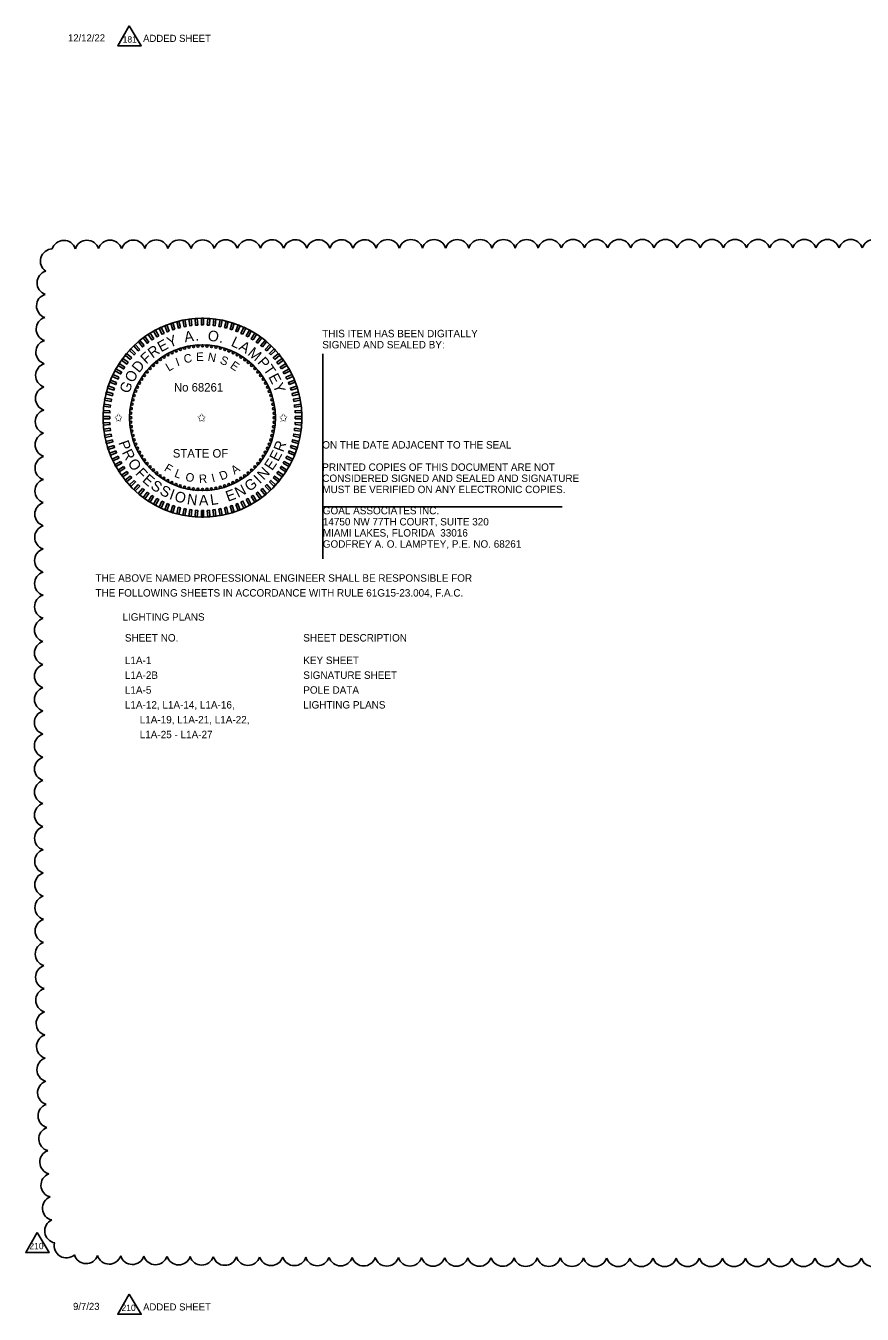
# Model space of a CAD drawing. Extents: x -811.2 to -795.1, y -2238.2 to -2204.
# Drawn here: x -811.16 to -803.27, y -2237.98 to -2225.83 of the extents above; entities that cross this region are included whole.
import ezdxf

# ---------------------------------------------------------------- set-up
doc = ezdxf.new("R2010")
doc.units = 0
for name, color, linetype in [('AdhocPoint_dp', 7, 'Continuous'), ('Cloud_dp', 7, 'Continuous'), ('PlotBorder_dp', 7, 'Continuous'), ('TextMinor', 7, 'Continuous'), ('TextMisc', 7, 'Continuous'), ('TextShtNo', 7, 'Continuous')]:
    doc.layers.add(name, color=color, linetype=linetype)

msp = doc.modelspace()

# ---------------------------------------------------------------- linework, layer by layer
at = {"layer": 'AdhocPoint_dp'}
for p, q in [((-808.355, -2228.92), (-808.355, -2230.855)), ((-808.355, -2230.365), (-806.098, -2230.365))]:
    msp.add_line(p, q, dxfattribs=at)
at = {"layer": 'Cloud_dp'}
for points in [[(-810.181, -2225.827), (-810.289, -2226.015), (-810.068, -2226.015)], [(-811.049, -2237.21), (-811.157, -2237.398), (-810.937, -2237.398)], [(-810.181, -2237.792), (-810.289, -2237.98), (-810.068, -2237.98)]]:
    msp.add_lwpolyline(points, close=True, dxfattribs=at)
for centre, start, end in [((-810.905, -2228.046), 91.4771, 236.4771), ((-810.798, -2227.965), 18.0566, 163.0566), ((-810.58, -2227.964), 17.7998, 162.7998), ((-810.362, -2227.963), 17.7187, 162.7187), ((-810.143, -2227.962), 17.6743, 162.6743), ((-809.925, -2227.961), 17.6451, 162.6451), ((-809.707, -2227.961), 17.624, 162.624), ((-809.488, -2227.961), 17.6079, 162.6079), ((-809.27, -2227.96), 17.5951, 162.5951), ((-809.052, -2227.96), 17.5845, 162.5845), ((-808.834, -2227.959), 17.5756, 162.5756), ((-808.615, -2227.959), 17.568, 162.568), ((-808.397, -2227.959), 17.5614, 162.5614), ((-808.179, -2227.959), 17.5556, 162.5556), ((-807.96, -2227.959), 17.5505, 162.5505), ((-807.742, -2227.958), 17.5459, 162.5459), ((-807.524, -2227.958), 17.5417, 162.5417), ((-807.305, -2227.958), 17.5379, 162.5379), ((-807.087, -2227.958), 17.5344, 162.5344), ((-806.869, -2227.958), 17.5313, 162.5313), ((-806.65, -2227.958), 17.5283, 162.5283), ((-806.432, -2227.958), 17.5256, 162.5256), ((-806.214, -2227.957), 17.5231, 162.5231), ((-805.995, -2227.957), 17.5207, 162.5207), ((-805.777, -2227.957), 17.5185, 162.5185), ((-805.559, -2227.957), 17.5164, 162.5164), ((-805.34, -2227.957), 17.5145, 162.5145), ((-805.122, -2227.957), 17.5126, 162.5126), ((-804.904, -2227.957), 17.5109, 162.5109), ((-804.685, -2227.957), 17.5092, 162.5092), ((-804.467, -2227.957), 17.5077, 162.5077), ((-804.249, -2227.957), 17.5062, 162.5062), ((-804.03, -2227.957), 17.5048, 162.5048), ((-803.812, -2227.957), 17.5034, 162.5034), ((-803.594, -2227.957), 17.5021, 162.5021), ((-803.375, -2227.957), 17.5009, 162.5009), ((-803.157, -2227.957), 17.5, 162.5), ((-810.937, -2228.252), 105.908, 250.908), ((-810.942, -2228.47), 106.4168, 251.4168), ((-810.945, -2228.688), 106.6762, 251.6762), ((-810.948, -2228.906), 106.841, 251.841), ((-810.95, -2229.124), 106.9576, 251.9576), ((-810.952, -2229.343), 107.0457, 252.0457), ((-810.954, -2229.561), 107.1154, 252.1154), ((-810.955, -2229.779), 107.1722, 252.1722), ((-810.956, -2229.998), 107.2198, 252.2198), ((-810.957, -2230.216), 107.2603, 252.2603), ((-810.958, -2230.434), 107.2954, 252.2954), ((-810.959, -2230.652), 107.3262, 252.3262), ((-810.96, -2230.871), 107.3535, 252.3535), ((-810.96, -2231.089), 107.3779, 252.3779), ((-810.96, -2231.307), 107.3998, 252.3998), ((-810.961, -2231.526), 107.4198, 252.4198), ((-810.961, -2231.744), 107.438, 252.438), ((-810.961, -2231.962), 107.4547, 252.4547), ((-810.961, -2232.181), 107.4701, 252.4701), ((-810.962, -2232.399), 107.4843, 252.4843), ((-810.962, -2232.617), 107.499, 252.499), ((-810.961, -2232.836), 107.5356, 252.5356), ((-810.961, -2233.054), 107.5822, 252.5822), ((-810.961, -2233.272), 107.6325, 252.6325), ((-810.96, -2233.49), 107.6869, 252.6869), ((-810.959, -2233.709), 107.7461, 252.7461), ((-810.958, -2233.927), 107.8108, 252.8108), ((-810.957, -2234.145), 107.8818, 252.8818), ((-810.955, -2234.364), 107.9604, 252.9604), ((-810.954, -2234.582), 108.0479, 253.0479), ((-810.951, -2234.8), 108.1461, 253.1461), ((-810.949, -2235.018), 108.2576, 253.2576), ((-810.945, -2235.237), 108.3854, 253.3854), ((-810.942, -2235.455), 108.534, 253.534), ((-810.938, -2235.673), 108.7099, 253.7099), ((-810.932, -2235.891), 108.9225, 253.9225), ((-810.927, -2236.109), 109.1867, 254.1867), ((-810.92, -2236.327), 109.5275, 254.5275), ((-810.911, -2236.545), 109.9909, 254.9909), ((-810.9, -2236.763), 110.6749, 255.6749), ((-810.886, -2236.98), 111.8417, 256.8417), ((-810.864, -2237.195), 114.6718, 259.6718), ((-810.774, -2237.335), 166.2299, 311.2299), ((-810.588, -2237.389), 196.1072, 341.1072), ((-810.37, -2237.394), 196.5738, 341.5738), ((-810.152, -2237.397), 196.7877, 341.7877), ((-809.934, -2237.399), 196.9179, 341.9179), ((-809.715, -2237.401), 197.008, 342.008), ((-809.497, -2237.403), 197.075, 342.075), ((-809.279, -2237.405), 197.1274, 342.1274), ((-809.061, -2237.406), 197.1699, 342.1699), ((-808.842, -2237.407), 197.2052, 342.2052), ((-808.624, -2237.408), 197.2352, 342.2352), ((-808.406, -2237.409), 197.261, 342.261), ((-808.187, -2237.41), 197.2836, 342.2836), ((-807.969, -2237.411), 197.3036, 342.3036), ((-807.751, -2237.412), 197.3214, 342.3214), ((-807.532, -2237.412), 197.3374, 342.3374), ((-807.314, -2237.413), 197.3519, 342.3519), ((-807.096, -2237.413), 197.3651, 342.3651), ((-806.878, -2237.414), 197.3773, 342.3773), ((-806.659, -2237.414), 197.3884, 342.3884), ((-806.441, -2237.415), 197.3987, 342.3987), ((-806.223, -2237.415), 197.4083, 342.4083), ((-806.004, -2237.415), 197.4172, 342.4172), ((-805.786, -2237.416), 197.4256, 342.4256), ((-805.568, -2237.416), 197.4334, 342.4334), ((-805.349, -2237.416), 197.4407, 342.4407), ((-805.131, -2237.417), 197.4476, 342.4476), ((-804.913, -2237.417), 197.4542, 342.4542), ((-804.694, -2237.417), 197.4604, 342.4604), ((-804.476, -2237.417), 197.4662, 342.4662), ((-804.258, -2237.417), 197.4718, 342.4718), ((-804.039, -2237.417), 197.4771, 342.4771), ((-803.821, -2237.417), 197.4821, 342.4821), ((-803.603, -2237.417), 197.487, 342.487), ((-803.384, -2237.417), 197.4916, 342.4916), ((-803.166, -2237.417), 197.496, 342.496)]:
    msp.add_arc(centre, 0.114, start, end, dxfattribs=at)
at = {"layer": 'TextMinor'}
for radius in [0.938, 0.688]:
    msp.add_circle((-809.49, -2229.524), radius, dxfattribs=at)
at = {"layer": 'TextShtNo'}
for p, q in [((-809.5, -2230.461), (-809.5, -2230.399)), ((-809.49, -2230.461), (-809.49, -2230.399)), ((-809.48, -2230.461), (-809.48, -2230.399))]:
    msp.add_line(p, q, dxfattribs=at)
for points in [[(-809.853, -2228.728), (-809.872, -2228.736), (-809.898, -2228.68), (-809.88, -2228.671)], [(-809.803, -2228.706), (-809.822, -2228.714), (-809.845, -2228.656), (-809.826, -2228.648)], [(-809.751, -2228.688), (-809.77, -2228.695), (-809.789, -2228.635), (-809.77, -2228.629)], [(-809.698, -2228.674), (-809.717, -2228.679), (-809.733, -2228.618), (-809.713, -2228.613)], [(-809.644, -2228.662), (-809.664, -2228.666), (-809.676, -2228.605), (-809.656, -2228.601)], [(-809.59, -2228.654), (-809.61, -2228.657), (-809.618, -2228.595), (-809.598, -2228.592)], [(-809.535, -2228.65), (-809.555, -2228.651), (-809.559, -2228.589), (-809.539, -2228.588)], [(-809.48, -2228.649), (-809.5, -2228.649), (-809.5, -2228.586), (-809.48, -2228.586)], [(-809.425, -2228.651), (-809.445, -2228.65), (-809.441, -2228.588), (-809.421, -2228.589)], [(-809.37, -2228.657), (-809.39, -2228.654), (-809.383, -2228.592), (-809.363, -2228.595)], [(-809.316, -2228.666), (-809.336, -2228.662), (-809.324, -2228.601), (-809.304, -2228.605)], [(-809.263, -2228.679), (-809.282, -2228.674), (-809.267, -2228.613), (-809.247, -2228.618)], [(-809.21, -2228.695), (-809.229, -2228.689), (-809.21, -2228.629), (-809.191, -2228.635)], [(-809.159, -2228.714), (-809.177, -2228.707), (-809.154, -2228.649), (-809.136, -2228.656)], [(-809.108, -2228.736), (-809.127, -2228.728), (-809.1, -2228.671), (-809.082, -2228.68)], [(-810.04, -2228.843), (-810.056, -2228.856), (-810.095, -2228.808), (-810.08, -2228.795)], [(-809.996, -2228.81), (-810.013, -2228.822), (-810.049, -2228.771), (-810.033, -2228.759)], [(-809.95, -2228.78), (-809.967, -2228.79), (-810.001, -2228.738), (-809.984, -2228.727)], [(-809.903, -2228.752), (-809.92, -2228.762), (-809.951, -2228.707), (-809.933, -2228.697)], [(-809.06, -2228.762), (-809.077, -2228.752), (-809.047, -2228.697), (-809.03, -2228.707)], [(-809.013, -2228.79), (-809.03, -2228.78), (-808.996, -2228.727), (-808.979, -2228.738)], [(-808.968, -2228.822), (-808.984, -2228.81), (-808.947, -2228.76), (-808.931, -2228.771)], [(-808.925, -2228.856), (-808.94, -2228.843), (-808.9, -2228.795), (-808.885, -2228.808)], [(-810.158, -2228.958), (-810.171, -2228.974), (-810.219, -2228.934), (-810.206, -2228.918)], [(-810.121, -2228.917), (-810.135, -2228.932), (-810.18, -2228.889), (-810.167, -2228.875)], [(-810.082, -2228.879), (-810.096, -2228.893), (-810.139, -2228.847), (-810.124, -2228.833)], [(-808.884, -2228.893), (-808.898, -2228.879), (-808.856, -2228.834), (-808.841, -2228.847)], [(-808.845, -2228.932), (-808.859, -2228.918), (-808.814, -2228.875), (-808.8, -2228.89)], [(-808.809, -2228.974), (-808.822, -2228.958), (-808.774, -2228.919), (-808.761, -2228.934)], [(-810.223, -2229.046), (-810.234, -2229.063), (-810.287, -2229.03), (-810.276, -2229.013)], [(-810.192, -2229.001), (-810.204, -2229.018), (-810.254, -2228.981), (-810.243, -2228.965)], [(-808.776, -2229.018), (-808.788, -2229.001), (-808.738, -2228.965), (-808.726, -2228.981)], [(-808.746, -2229.064), (-808.757, -2229.047), (-808.704, -2229.013), (-808.693, -2229.03)], [(-810.278, -2229.142), (-810.286, -2229.16), (-810.343, -2229.134), (-810.334, -2229.115)], [(-810.252, -2229.093), (-810.262, -2229.111), (-810.316, -2229.081), (-810.307, -2229.063)], [(-808.718, -2229.111), (-808.728, -2229.094), (-808.673, -2229.063), (-808.664, -2229.081)], [(-808.694, -2229.16), (-808.703, -2229.142), (-808.646, -2229.116), (-808.638, -2229.134)], [(-810.335, -2229.296), (-810.34, -2229.316), (-810.401, -2229.3), (-810.396, -2229.281)], [(-810.319, -2229.244), (-810.325, -2229.263), (-810.385, -2229.244), (-810.379, -2229.224)], [(-810.3, -2229.192), (-810.307, -2229.211), (-810.365, -2229.188), (-810.358, -2229.169)], [(-808.673, -2229.211), (-808.68, -2229.192), (-808.622, -2229.169), (-808.615, -2229.188)], [(-808.655, -2229.263), (-808.661, -2229.244), (-808.602, -2229.225), (-808.595, -2229.244)], [(-808.64, -2229.316), (-808.645, -2229.297), (-808.585, -2229.281), (-808.58, -2229.301)], [(-810.357, -2229.404), (-810.36, -2229.424), (-810.421, -2229.416), (-810.419, -2229.396)], [(-810.348, -2229.35), (-810.352, -2229.37), (-810.413, -2229.358), (-810.409, -2229.338)], [(-808.629, -2229.37), (-808.632, -2229.35), (-808.571, -2229.338), (-808.567, -2229.358)], [(-808.621, -2229.424), (-808.623, -2229.404), (-808.561, -2229.396), (-808.559, -2229.416)], [(-810.365, -2229.514), (-810.365, -2229.534), (-810.428, -2229.534), (-810.428, -2229.514)], [(-810.363, -2229.459), (-810.364, -2229.479), (-810.426, -2229.475), (-810.425, -2229.455)], [(-808.616, -2229.479), (-808.617, -2229.459), (-808.555, -2229.455), (-808.554, -2229.475)], [(-808.615, -2229.534), (-808.615, -2229.514), (-808.553, -2229.514), (-808.553, -2229.534)], [(-810.364, -2229.569), (-810.363, -2229.589), (-810.425, -2229.593), (-810.426, -2229.573)], [(-810.36, -2229.623), (-810.357, -2229.643), (-810.419, -2229.651), (-810.421, -2229.631)], [(-808.623, -2229.644), (-808.621, -2229.624), (-808.559, -2229.631), (-808.561, -2229.651)], [(-808.617, -2229.589), (-808.616, -2229.569), (-808.554, -2229.573), (-808.555, -2229.593)], [(-810.352, -2229.678), (-810.348, -2229.698), (-810.409, -2229.709), (-810.413, -2229.689)], [(-810.34, -2229.732), (-810.335, -2229.751), (-810.396, -2229.767), (-810.401, -2229.747)], [(-808.645, -2229.751), (-808.64, -2229.732), (-808.58, -2229.747), (-808.585, -2229.767)], [(-808.632, -2229.698), (-808.629, -2229.678), (-808.567, -2229.69), (-808.571, -2229.709)], [(-810.325, -2229.785), (-810.319, -2229.804), (-810.379, -2229.823), (-810.385, -2229.804)], [(-810.307, -2229.836), (-810.3, -2229.855), (-810.358, -2229.878), (-810.366, -2229.859)], [(-810.286, -2229.887), (-810.278, -2229.905), (-810.334, -2229.932), (-810.343, -2229.914)], [(-808.703, -2229.906), (-808.694, -2229.887), (-808.638, -2229.914), (-808.646, -2229.932)], [(-808.68, -2229.855), (-808.673, -2229.837), (-808.615, -2229.86), (-808.622, -2229.878)], [(-808.661, -2229.804), (-808.655, -2229.785), (-808.595, -2229.804), (-808.602, -2229.823)], [(-810.262, -2229.936), (-810.252, -2229.954), (-810.307, -2229.984), (-810.317, -2229.967)], [(-810.234, -2229.984), (-810.224, -2230.001), (-810.276, -2230.035), (-810.287, -2230.018)], [(-808.757, -2230.001), (-808.746, -2229.984), (-808.693, -2230.018), (-808.704, -2230.035)], [(-808.728, -2229.954), (-808.719, -2229.937), (-808.664, -2229.967), (-808.674, -2229.984)], [(-810.204, -2230.03), (-810.192, -2230.046), (-810.243, -2230.083), (-810.255, -2230.067)], [(-810.171, -2230.074), (-810.158, -2230.089), (-810.206, -2230.129), (-810.219, -2230.114)], [(-810.135, -2230.115), (-810.121, -2230.13), (-810.167, -2230.173), (-810.18, -2230.158)], [(-808.859, -2230.13), (-808.845, -2230.116), (-808.8, -2230.158), (-808.814, -2230.173)], [(-808.822, -2230.089), (-808.81, -2230.074), (-808.761, -2230.114), (-808.774, -2230.129)], [(-808.788, -2230.046), (-808.776, -2230.03), (-808.726, -2230.067), (-808.738, -2230.083)], [(-810.097, -2230.155), (-810.082, -2230.169), (-810.125, -2230.214), (-810.139, -2230.2)], [(-810.056, -2230.192), (-810.04, -2230.204), (-810.08, -2230.253), (-810.096, -2230.24)], [(-810.013, -2230.226), (-809.996, -2230.238), (-810.033, -2230.288), (-810.049, -2230.276)], [(-808.984, -2230.238), (-808.968, -2230.226), (-808.931, -2230.276), (-808.947, -2230.288)], [(-808.94, -2230.205), (-808.925, -2230.192), (-808.885, -2230.24), (-808.9, -2230.253)], [(-808.899, -2230.169), (-808.884, -2230.155), (-808.841, -2230.2), (-808.856, -2230.214)], [(-809.968, -2230.257), (-809.951, -2230.268), (-809.984, -2230.321), (-810.001, -2230.31)], [(-809.921, -2230.286), (-809.903, -2230.295), (-809.933, -2230.35), (-809.951, -2230.34)], [(-809.872, -2230.311), (-809.854, -2230.32), (-809.88, -2230.376), (-809.898, -2230.368)], [(-809.822, -2230.334), (-809.803, -2230.341), (-809.826, -2230.399), (-809.845, -2230.392)], [(-809.77, -2230.353), (-809.751, -2230.359), (-809.77, -2230.419), (-809.789, -2230.412)], [(-809.718, -2230.369), (-809.698, -2230.374), (-809.714, -2230.434), (-809.733, -2230.429)], [(-809.282, -2230.374), (-809.263, -2230.369), (-809.247, -2230.429), (-809.267, -2230.434)], [(-809.229, -2230.359), (-809.21, -2230.353), (-809.191, -2230.412), (-809.21, -2230.419)], [(-809.177, -2230.341), (-809.159, -2230.334), (-809.136, -2230.392), (-809.154, -2230.399)], [(-809.127, -2230.32), (-809.108, -2230.311), (-809.082, -2230.368), (-809.1, -2230.376)], [(-809.077, -2230.296), (-809.06, -2230.286), (-809.03, -2230.341), (-809.047, -2230.35)], [(-809.03, -2230.268), (-809.013, -2230.257), (-808.979, -2230.31), (-808.996, -2230.321)], [(-809.664, -2230.381), (-809.644, -2230.385), (-809.656, -2230.447), (-809.676, -2230.443)], [(-809.61, -2230.391), (-809.59, -2230.393), (-809.598, -2230.455), (-809.618, -2230.453)], [(-809.555, -2230.396), (-809.535, -2230.398), (-809.539, -2230.46), (-809.559, -2230.459)], [(-809.5, -2230.399), (-809.48, -2230.399), (-809.48, -2230.461), (-809.5, -2230.461)], [(-809.445, -2230.398), (-809.425, -2230.397), (-809.421, -2230.459), (-809.441, -2230.46)], [(-809.391, -2230.393), (-809.371, -2230.391), (-809.363, -2230.453), (-809.383, -2230.455)], [(-809.336, -2230.385), (-809.316, -2230.381), (-809.305, -2230.443), (-809.324, -2230.447)]]:
    msp.add_lwpolyline(points, close=True, dxfattribs=at)
for centre in [(-809.778, -2228.911), (-809.739, -2228.894), (-809.699, -2228.879), (-809.658, -2228.868), (-809.617, -2228.858), (-809.574, -2228.852), (-809.532, -2228.848), (-809.49, -2228.846), (-809.447, -2228.848), (-809.405, -2228.852), (-809.363, -2228.858), (-809.321, -2228.868), (-809.28, -2228.88), (-809.24, -2228.894), (-809.201, -2228.911), (-809.953, -2229.03), (-809.922, -2229.001), (-809.888, -2228.975), (-809.853, -2228.952), (-809.816, -2228.93), (-809.163, -2228.93), (-809.127, -2228.952), (-809.091, -2228.976), (-809.058, -2229.002), (-809.026, -2229.03), (-810.062, -2229.16), (-810.038, -2229.125), (-810.012, -2229.092), (-809.984, -2229.06), (-808.996, -2229.06), (-808.968, -2229.092), (-808.942, -2229.126), (-808.918, -2229.161), (-810.12, -2229.274), (-810.103, -2229.235), (-810.084, -2229.197), (-808.896, -2229.198), (-808.877, -2229.236), (-808.86, -2229.275), (-810.155, -2229.396), (-810.146, -2229.355), (-810.134, -2229.314), (-808.846, -2229.315), (-808.834, -2229.356), (-808.825, -2229.397), (-810.168, -2229.523), (-810.166, -2229.481), (-810.162, -2229.438), (-808.818, -2229.439), (-808.814, -2229.482), (-808.813, -2229.524), (-810.166, -2229.566), (-810.162, -2229.608), (-810.156, -2229.65), (-808.825, -2229.651), (-808.818, -2229.609), (-808.814, -2229.567), (-810.146, -2229.692), (-810.135, -2229.733), (-810.12, -2229.773), (-808.86, -2229.774), (-808.846, -2229.734), (-808.834, -2229.693), (-810.103, -2229.812), (-810.084, -2229.85), (-810.062, -2229.886), (-808.918, -2229.887), (-808.897, -2229.851), (-808.877, -2229.813), (-810.039, -2229.922), (-810.012, -2229.955), (-809.984, -2229.987), (-809.954, -2230.017), (-809.027, -2230.018), (-808.997, -2229.988), (-808.968, -2229.956), (-808.942, -2229.922), (-809.922, -2230.045), (-809.889, -2230.072), (-809.854, -2230.096), (-809.817, -2230.117), (-809.779, -2230.137), (-809.202, -2230.137), (-809.164, -2230.118), (-809.128, -2230.096), (-809.092, -2230.072), (-809.059, -2230.046), (-809.74, -2230.154), (-809.7, -2230.168), (-809.659, -2230.18), (-809.618, -2230.189), (-809.576, -2230.196), (-809.533, -2230.2), (-809.49, -2230.201), (-809.448, -2230.2), (-809.406, -2230.196), (-809.364, -2230.189), (-809.322, -2230.18), (-809.281, -2230.168), (-809.241, -2230.154)]:
    msp.add_circle(centre, 0.01, dxfattribs=at)

# ---------------------------------------------------------------- texts
at = {"layer": 'Cloud_dp'}
for s, p in [('181', (-810.243, -2225.985)), ('210', (-811.123, -2237.367)), ('210', (-810.254, -2237.95))]:
    msp.add_text(s, height=0.06, rotation=0, dxfattribs=at).set_placement(p)
at = {"layer": 'PlotBorder_dp'}
for s, p in [('THIS ITEM HAS BEEN DIGITALLY', (-808.36, -2228.765)), ('SIGNED AND SEALED BY:', (-808.36, -2228.87)), ('ON THE DATE ADJACENT TO THE SEAL', (-808.36, -2229.815)), ('PRINTED COPIES OF THIS DOCUMENT ARE NOT ', (-808.36, -2230.025)), ('CONSIDERED SIGNED AND SEALED AND SIGNATURE ', (-808.36, -2230.13)), ('MUST BE VERIFIED ON ANY ELECTRONIC COPIES.', (-808.36, -2230.235)), ('GOAL ASSOCIATES INC.', (-808.355, -2230.435)), ('14750 NW 77TH COURT, SUITE 320', (-808.355, -2230.54)), ('MIAMI LAKES, FLORIDA  33016', (-808.355, -2230.645)), ('GODFREY A. O. LAMPTEY, P.E. NO. 68261', (-808.355, -2230.75)), ('THE ABOVE NAMED PROFESSIONAL ENGINEER SHALL BE RESPONSIBLE FOR ', (-810.499, -2231.071)), ('THE FOLLOWING SHEETS IN ACCORDANCE WITH RULE 61G15-23.004, F.A.C.', (-810.499, -2231.211)), ('LIGHTING PLANS', (-810.245, -2231.438))]:
    msp.add_text(s, height=0.07, dxfattribs=at).set_placement(p)
at = {"layer": 'TextMinor'}
for s, p in [('12/12/22', (-810.759, -2225.975)), ('9/7/23', (-810.711, -2237.94)), ('ADDED SHEET', (-810.05, -2237.945))]:
    msp.add_text(s, height=0.0672, rotation=360, dxfattribs=at).set_placement(p)
msp.add_text('ADDED SHEET', height=0.0672, dxfattribs=at).set_placement((-810.05, -2225.979))
at = {"layer": 'TextMisc'}
for s, p in [('SHEET NO.', (-810.222, -2231.635)), ('SHEET DESCRIPTION', (-808.539, -2231.635)), ('L1A-1', (-810.222, -2231.847)), ('KEY SHEET', (-808.539, -2231.847)), ('L1A-2B', (-810.222, -2231.987)), ('SIGNATURE SHEET', (-808.539, -2231.987)), ('L1A-5', (-810.222, -2232.127)), ('POLE DATA', (-808.539, -2232.127)), ('L1A-12, L1A-14, L1A-16,', (-810.222, -2232.267)), ('LIGHTING PLANS', (-808.539, -2232.267)), ('L1A-19, L1A-21, L1A-22,', (-810.082, -2232.407)), ('L1A-25 - L1A-27', (-810.082, -2232.547))]:
    msp.add_text(s, height=0.07, dxfattribs=at).set_placement(p)
at = {"layer": 'TextShtNo'}
for s, height, rotation, p in [('E', 0.1, 28.1055, (-809.881, -2228.908)), ('Y', 0.1, 21.0633, (-809.802, -2228.864)), ('A', 0.1, 8.8088, (-809.655, -2228.813)), ('.', 0.1, 1.0418, (-809.558, -2228.797)), ('O', 0.1, 352.1877, (-809.445, -2228.796)), ('L', 0.1, 334.6727, (-809.228, -2228.843)), ('F', 0.1, 42.3772, (-810.02, -2229.023)), ('R', 0.1, 35.9269, (-809.961, -2228.967)), ('E', 0.08, 0.4186, (-809.55, -2228.989)), ('N', 0.08, 349.2914, (-809.445, -2228.987)), ('.', 0.1, 343.5268, (-809.336, -2228.811)), ('A', 0.1, 328.4096, (-809.155, -2228.876)), ('M', 0.1, 320.6426, (-809.071, -2228.927)), ('D', 0.1, 50.8569, (-810.089, -2229.107)), ('L', 0.08, 30.4021, (-809.809, -2229.09)), ('I', 0.08, 20.0117, (-809.726, -2229.04)), ('C', 0.08, 12.2025, (-809.658, -2229.012)), ('S', 0.08, 337.0221, (-809.332, -2229.009)), ('E', 0.08, 325.8663, (-809.236, -2229.049)), ('P', 0.1, 311.1966, (-808.978, -2229.004)), ('T', 0.1, 304.4563, (-808.921, -2229.068)), ('O', 0.1, 59.5178, (-810.145, -2229.201)), ('E', 0.1, 297.6315, (-808.871, -2229.138)), ('G', 0.1, 68.0518, (-810.185, -2229.302)), ('Y', 0.1, 290.5893, (-808.828, -2229.217)), ('P', 0.1, 289.4055, (-810.285, -2229.758)), ('R', 0.1, 69.5134, (-808.73, -2229.854)), ('R', 0.1, 296.1458, (-810.252, -2229.85)), ('E', 0.1, 62.4712, (-808.776, -2229.944)), ('O', 0.1, 303.9671, (-810.2, -2229.951)), ('F', 0.1, 312.628, (-810.128, -2230.053)), ('F', 0.08, 328.7241, (-809.858, -2230.02)), ('L', 0.08, 339.2916, (-809.761, -2230.079)), ('A', 0.08, 34.4992, (-809.188, -2230.063)), ('N', 0.1, 47.1788, (-808.912, -2230.118)), ('E', 0.1, 55.4289, (-808.833, -2230.029)), ('E', 0.1, 319.0783, (-810.064, -2230.121)), ('S', 0.1, 326.1206, (-809.987, -2230.187)), ('O', 0.08, 349.6821, (-809.656, -2230.119)), ('R', 0.08, 2.3398, (-809.522, -2230.141)), ('I', 0.08, 14.2037, (-809.394, -2230.134)), ('D', 0.08, 22.0128, (-809.312, -2230.116)), ('G', 0.1, 35.1115, (-809.049, -2230.225)), ('I', 0.1, 43.6456, (-808.95, -2230.152)), ('S', 0.1, 333.193, (-809.902, -2230.243)), ('I', 0.1, 340.2654, (-809.81, -2230.288)), ('O', 0.1, 343.7986, (-809.762, -2230.307)), ('N', 0.1, 352.4595, (-809.641, -2230.339)), ('A', 0.1, 0.7097, (-809.523, -2230.352)), ('L', 0.1, 8.4767, (-809.41, -2230.349)), ('E', 0.1, 19.8191, (-809.25, -2230.317)), ('N', 0.1, 26.8614, (-809.154, -2230.281))]:
    msp.add_text(s, height=height, rotation=rotation, dxfattribs=at).set_placement(p)
for s, p in [('No 68261', (-809.759, -2229.277)), ('✩', (-810.325, -2229.562)), ('✩', (-809.54, -2229.562)), ('✩', (-808.769, -2229.562)), ('STATE OF', (-809.77, -2229.9))]:
    msp.add_text(s, height=0.08, dxfattribs=at).set_placement(p)

doc.saveas('drawing.dxf')
